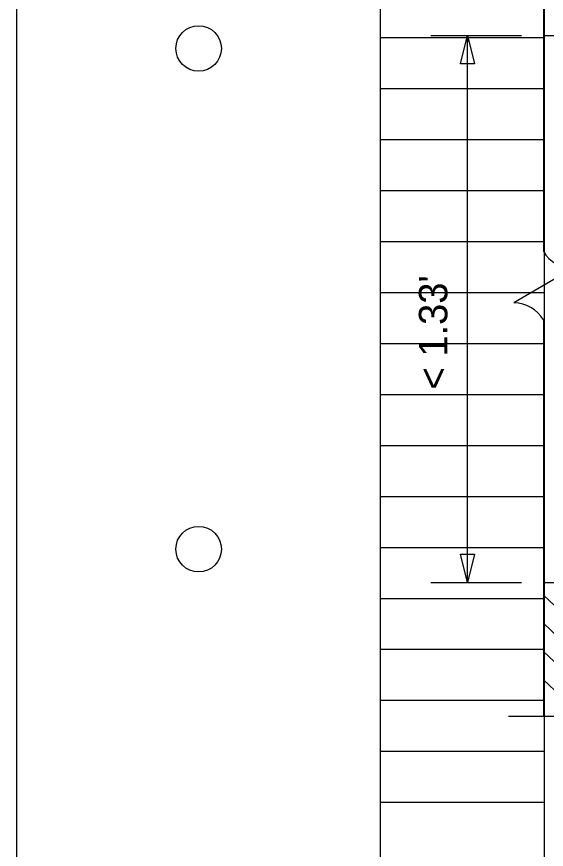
# Model space of a CAD drawing. Extents: x 0 to 34, y 0 to 22.
# Drawn here: x 0 to 2.911, y 13.601 to 18.175 of the extents above; entities that cross this region are included whole.
import ezdxf

# ---------------------------------------------------------------- set-up
doc = ezdxf.new("R2010")
doc.units = 0
for name, color, linetype in [('Default', 7, 'Continuous'), ('SC_Scratch1', 7, 'Continuous'), ('SH_Border', 7, 'Continuous'), ('SH_Cut_Line', 7, 'Continuous')]:
    doc.layers.add(name, color=color, linetype=linetype)

msp = doc.modelspace()

# ---------------------------------------------------------------- linework, layer by layer
at = {"layer": 'Default'}
for p, q in [((2.8946, 19.0284), (2.8946, 16.8858)), ((2.2755, 18.071), (2.7746, 18.071)), ((2.4778, 15.0663), (2.4778, 18.071)), ((2.4778, 18.071), (2.4778, 18.0368)), ((2.8946, 18.071), (8.1508, 18.071)), ((3.0568, 16.793), (2.7323, 16.6022)), ((2.8946, 16.5094), (2.8946, 15.0663)), ((2.4778, 15.0663), (2.4778, 15.4003)), ((2.2755, 15.0663), (2.7746, 15.0663)), ((2.8946, 15.0663), (8.1508, 15.0663)), ((2.8946, 15.0663), (2.8946, 14.3331)), ((2.8946, 14.9981), (3.5965, 14.3331)), ((2.8946, 14.8432), (3.4329, 14.3331)), ((2.8946, 14.6882), (3.2693, 14.3331)), ((2.8946, 14.5332), (3.1057, 14.3331)), ((2.7025, 14.3331), (5.5143, 14.3331))]:
    msp.add_line(p, q, dxfattribs=at)
for points in [[(2.4388, 17.915), (2.4778, 18.071), (2.5168, 17.915)], [(2.5168, 15.2223), (2.4778, 15.0663), (2.4388, 15.2223)]]:
    msp.add_lwpolyline(points, close=True, dxfattribs=at)
for centre, start, end in [((3.0568, 16.9812), 210.4422, 270), ((2.7323, 16.414), 30.4422, 90)]:
    msp.add_arc(centre, 0.1882, start, end, dxfattribs=at)
at = {"layer": 'SC_Scratch1'}
for p, q in [((2, 0.98), (2, 21.14)), ((2.9, 0.98), (2.9, 21.14)), ((2, 18.06), (2.9, 18.06)), ((2, 17.78), (2.9, 17.78)), ((2, 17.5), (2.9, 17.5)), ((2, 17.22), (2.9, 17.22)), ((2, 16.94), (2.9, 16.94)), ((2, 16.66), (2.9, 16.66)), ((2, 16.38), (2.9, 16.38)), ((2, 16.1), (2.9, 16.1)), ((2, 15.82), (2.9, 15.82)), ((2, 15.54), (2.9, 15.54)), ((2, 15.26), (2.9, 15.26)), ((2, 14.98), (2.9, 14.98)), ((2, 14.7), (2.9, 14.7)), ((2, 14.42), (2.9, 14.42)), ((2, 14.14), (2.9, 14.14)), ((2, 13.86), (2.9, 13.86))]:
    msp.add_line(p, q, dxfattribs=at)
at = {"layer": 'SH_Border'}
msp.add_lwpolyline([(2, 21.5), (33.5, 21.5), (33.5, 0.5), (2, 0.5)], close=True, dxfattribs=at)
for centre in [(1, 18), (1, 15.25)]:
    msp.add_circle(centre, 0.125, dxfattribs=at)
at = {"layer": 'SH_Cut_Line'}
msp.add_lwpolyline([(0, 0), (34, 0), (34, 22), (0, 22)], close=True, dxfattribs=at)

# ---------------------------------------------------------------- texts
at = {"layer": 'Default'}
msp.add_text("< 1.33'", height=0.15649, rotation=90, dxfattribs=at).set_placement((2.3668, 16.1268))

doc.saveas('drawing.dxf')
